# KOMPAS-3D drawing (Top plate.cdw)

Views: View 1, Front, View 3, Isometric YZX
Referenced files in C:\Work\01 К О М П А С\Модели примеры\2009_04_For_Poland_AXAPACK\My sample\: Top_plate.a3d, Top_plate.m3d, rail4.m3d
Referenced files in D:\Documents and Settings\kashirsky\Рабочий стол\: GRAPHIC_DE.LYT
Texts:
  Assembly
  Drawing Annotation
  Dimension Texts
  Surface Finish
  Leader #1
  Leader #2
  Leader #3
  Shape Deviations and Datum
  Table Header
  Table Cell
  Cut/Section Line
  Direction Arrow
  Modification Symbol
  Brace
  Node point number
  Mark of coordination axis
  VRCB
  Leader Text
  Node point designation
  Mark/Reference designation with leader
  Mark/reference designation on line
  Mark/Reference designation without leader
  System Layer
  System View
  Projection View 2
  Specifications
  Unspecified Surface Finish
  BOM table name
  Top plate
  Rail
Dimensions and other numbers on the sheet: 7; 3000; 1820; 1:1; 1; 1135,11; 0; 2; 3; 4; 5; 6; 8; 9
